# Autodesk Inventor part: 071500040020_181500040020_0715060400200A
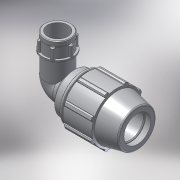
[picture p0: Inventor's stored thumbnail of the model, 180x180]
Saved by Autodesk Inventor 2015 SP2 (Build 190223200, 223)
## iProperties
Created: 2017-02
Part Number: 071500040020_181500040020_0715060400200A
Material: PVC-Piping
Description: PLASSON 90° ELBOW FEMALE ADAPTOR 40-2"
Document SubType Name: Modeling
Designer: KIM
Mass: 92.6774 g
Surface Area: 199.44 cm^2
Volume: 66.1981 cm^3
Density: 1.4 g/cm^3
Appearance: Smooth - White
Author: KIM
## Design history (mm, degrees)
derived "07150.ipt"
feature "Solid1::07150.ipt"
tag "TaggingFeature1"
body "Solid1"
other parameters: "d4" = 9.91667, "d5" = 29.75, "d7" = 82, "d9" = 17, "d11" = 3.96667, "d13" = 120 deg, "d14" = 56, "d15" = 12 deg, "d16" = 77.9, "d18" = 2, "d19" = 35 deg, "d20" = 17.5 deg, "d21" = 76.26, "d23" = 0, "d25" = 360 deg, "d27" = 1.64, "d33" = 0.8, "d42" = 44.03, "d43" = 2.46, "d46" = 1.2, "d51" = 119, "d68" = 3.96667, "d72" = 75, "d73" = 73.6528, "d75" = 84.70072, "d76" = 56.656, "d77" = 33, "d79" = 22.6624, "d80" = 1.69968, "d83" = 0, "d84" = 0, "d91" = 73.8, "d93" = 84, "d94" = 56.656, "d95" = 39.6592, "d96" = 11.9, "d97" = 50 deg, "d98" = 50.9904, "d99" = 0.5, "d100" = 0.5, "d101" = 10, "d102" = 73.6528, "d103" = 25.5, "d104" = 0, "d108" = 360 deg, "d110" = 2.20958, "E_" = 82, "A_" = 119, "l_" = 84, "A_1" = 75, "Rp_" = 56.656, "d105" = 11.04792
